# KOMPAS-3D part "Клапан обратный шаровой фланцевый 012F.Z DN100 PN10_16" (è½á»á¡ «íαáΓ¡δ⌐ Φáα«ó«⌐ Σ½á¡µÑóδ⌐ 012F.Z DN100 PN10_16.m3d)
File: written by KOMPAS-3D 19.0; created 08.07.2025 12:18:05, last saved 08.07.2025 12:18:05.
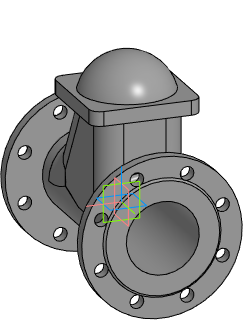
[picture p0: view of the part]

Document properties: Полное имя файла: E:\Dendor Работа Сачек\3D для проектировщиков\5.3 Тип 012F, 012F.Z Клапан обратный шаровой фланцевый\stp_Клапан обратный шаровой фланцевый 012F.Z PN10_16\Клапан обратный шаровой фланцевый 012F.Z DN100 PN10_16.m3d

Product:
- Part/product: Клапан обратный шаровой фланцевый 012F.Z DN100 PN10_16

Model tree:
1. Операция без истории:1  (labels: Клапан обратный шаровой фланцевый 012F.Z DN100 PN10_16)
